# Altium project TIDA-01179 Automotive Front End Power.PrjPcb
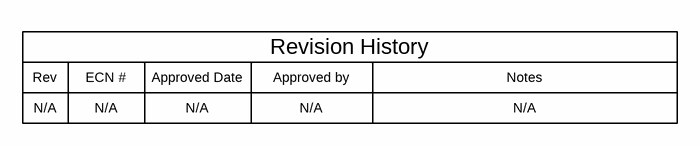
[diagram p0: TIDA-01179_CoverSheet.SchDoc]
CopyrightYear: 2016; PCB_Layout: X.Gong; PCB_Rev: E1; PRJ_Customer: Public Release; PRJ_Engineer: X.Gong; PRJ_Number: TIDA-01179; PRJ_Title: Automotive Wide Vin 30W Front-End Power Reference Design for 12V Car Battery; SCH_Rev: E1; TechSupport: http://www.ti.com/support; TID: 01179
4 sheets, 142 parts. Net scope: global (net labels, ports and power ports of the same name join across sheets).
Board file: TIDA-01179_Project_PCB.PcbDoc
Sheets:
  TIDA-01179_CoverSheet.SchDoc
  TIDA-01179_DCDC_Converters.SchDoc
  TIDA-01179_Reverse_Polarity_Protection.SchDoc
  TIDA-01179_Hardware.SchDoc

## Sheet TIDA-01179_CoverSheet.SchDoc: CoverSheet
size 431 x 279 mm; Date: Not shown in title block; ApprovedBy: Not shown in title block; CheckedBy: Not shown in title block; Author: Not shown in title block; CompanyName: Not shown in title block; DrawnBy: X.Gong; Engineer: Not shown in title block; Organization: Not shown in title block; Address1: Not shown in title block; Address2: Not shown in title block; Address3: Not shown in title block; Address4: Not shown in title block; DocumentNumber: 1; Revision: Use project parameter SCH_Rev; SheetNumber: 1; SheetTotal: 3; PageSetup: Record=PageOptions¦CenterHorizontal=True¦CenterVertical=True¦PrintScale=1.00¦XCorrection=1.00¦YCorrection=1.00¦PrintKind=0¦BorderSize=5000000¦LeftOffset=0¦BottomOffset=0¦Orientation=2¦PaperLength=1000¦PaperWidth=1000¦Scale=100¦PaperSource=15¦PrintQuality=600¦MediaType=1¦DitherType=10¦PaperKind=Letter¦PrintScaleMode=1

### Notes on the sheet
- Rev
- N/A
- ECN #
- Approved Date
- Approved by
- Revision History
- Notes

## Sheet TIDA-01179_DCDC_Converters.SchDoc: DCDC_Converters
size 431 x 279 mm; Date: Not shown in title block; ApprovedBy: Not shown in title block; CheckedBy: Not shown in title block; Author: Not shown in title block; CompanyName: Not shown in title block; DrawnBy: X.Gong; Engineer: Not shown in title block; Organization: Not shown in title block; Address1: Not shown in title block; Address2: Not shown in title block; Address3: Not shown in title block; Address4: Not shown in title block; DocumentNumber: 2; Revision: Use project parameter SCH_Rev; SheetNumber: 2; SheetTotal: 3; PageSetup: Record=PageOptions¦CenterHorizontal=True¦CenterVertical=True¦PrintScale=1.00¦XCorrection=1.00¦YCorrection=1.00¦PrintKind=0¦BorderSize=5000000¦LeftOffset=0¦BottomOffset=0¦Orientation=2¦PaperLength=1000¦PaperWidth=1000¦Scale=100¦PaperSource=15¦PrintQuality=600¦MediaType=1¦DitherType=10¦PaperKind=Letter¦PrintScaleMode=1
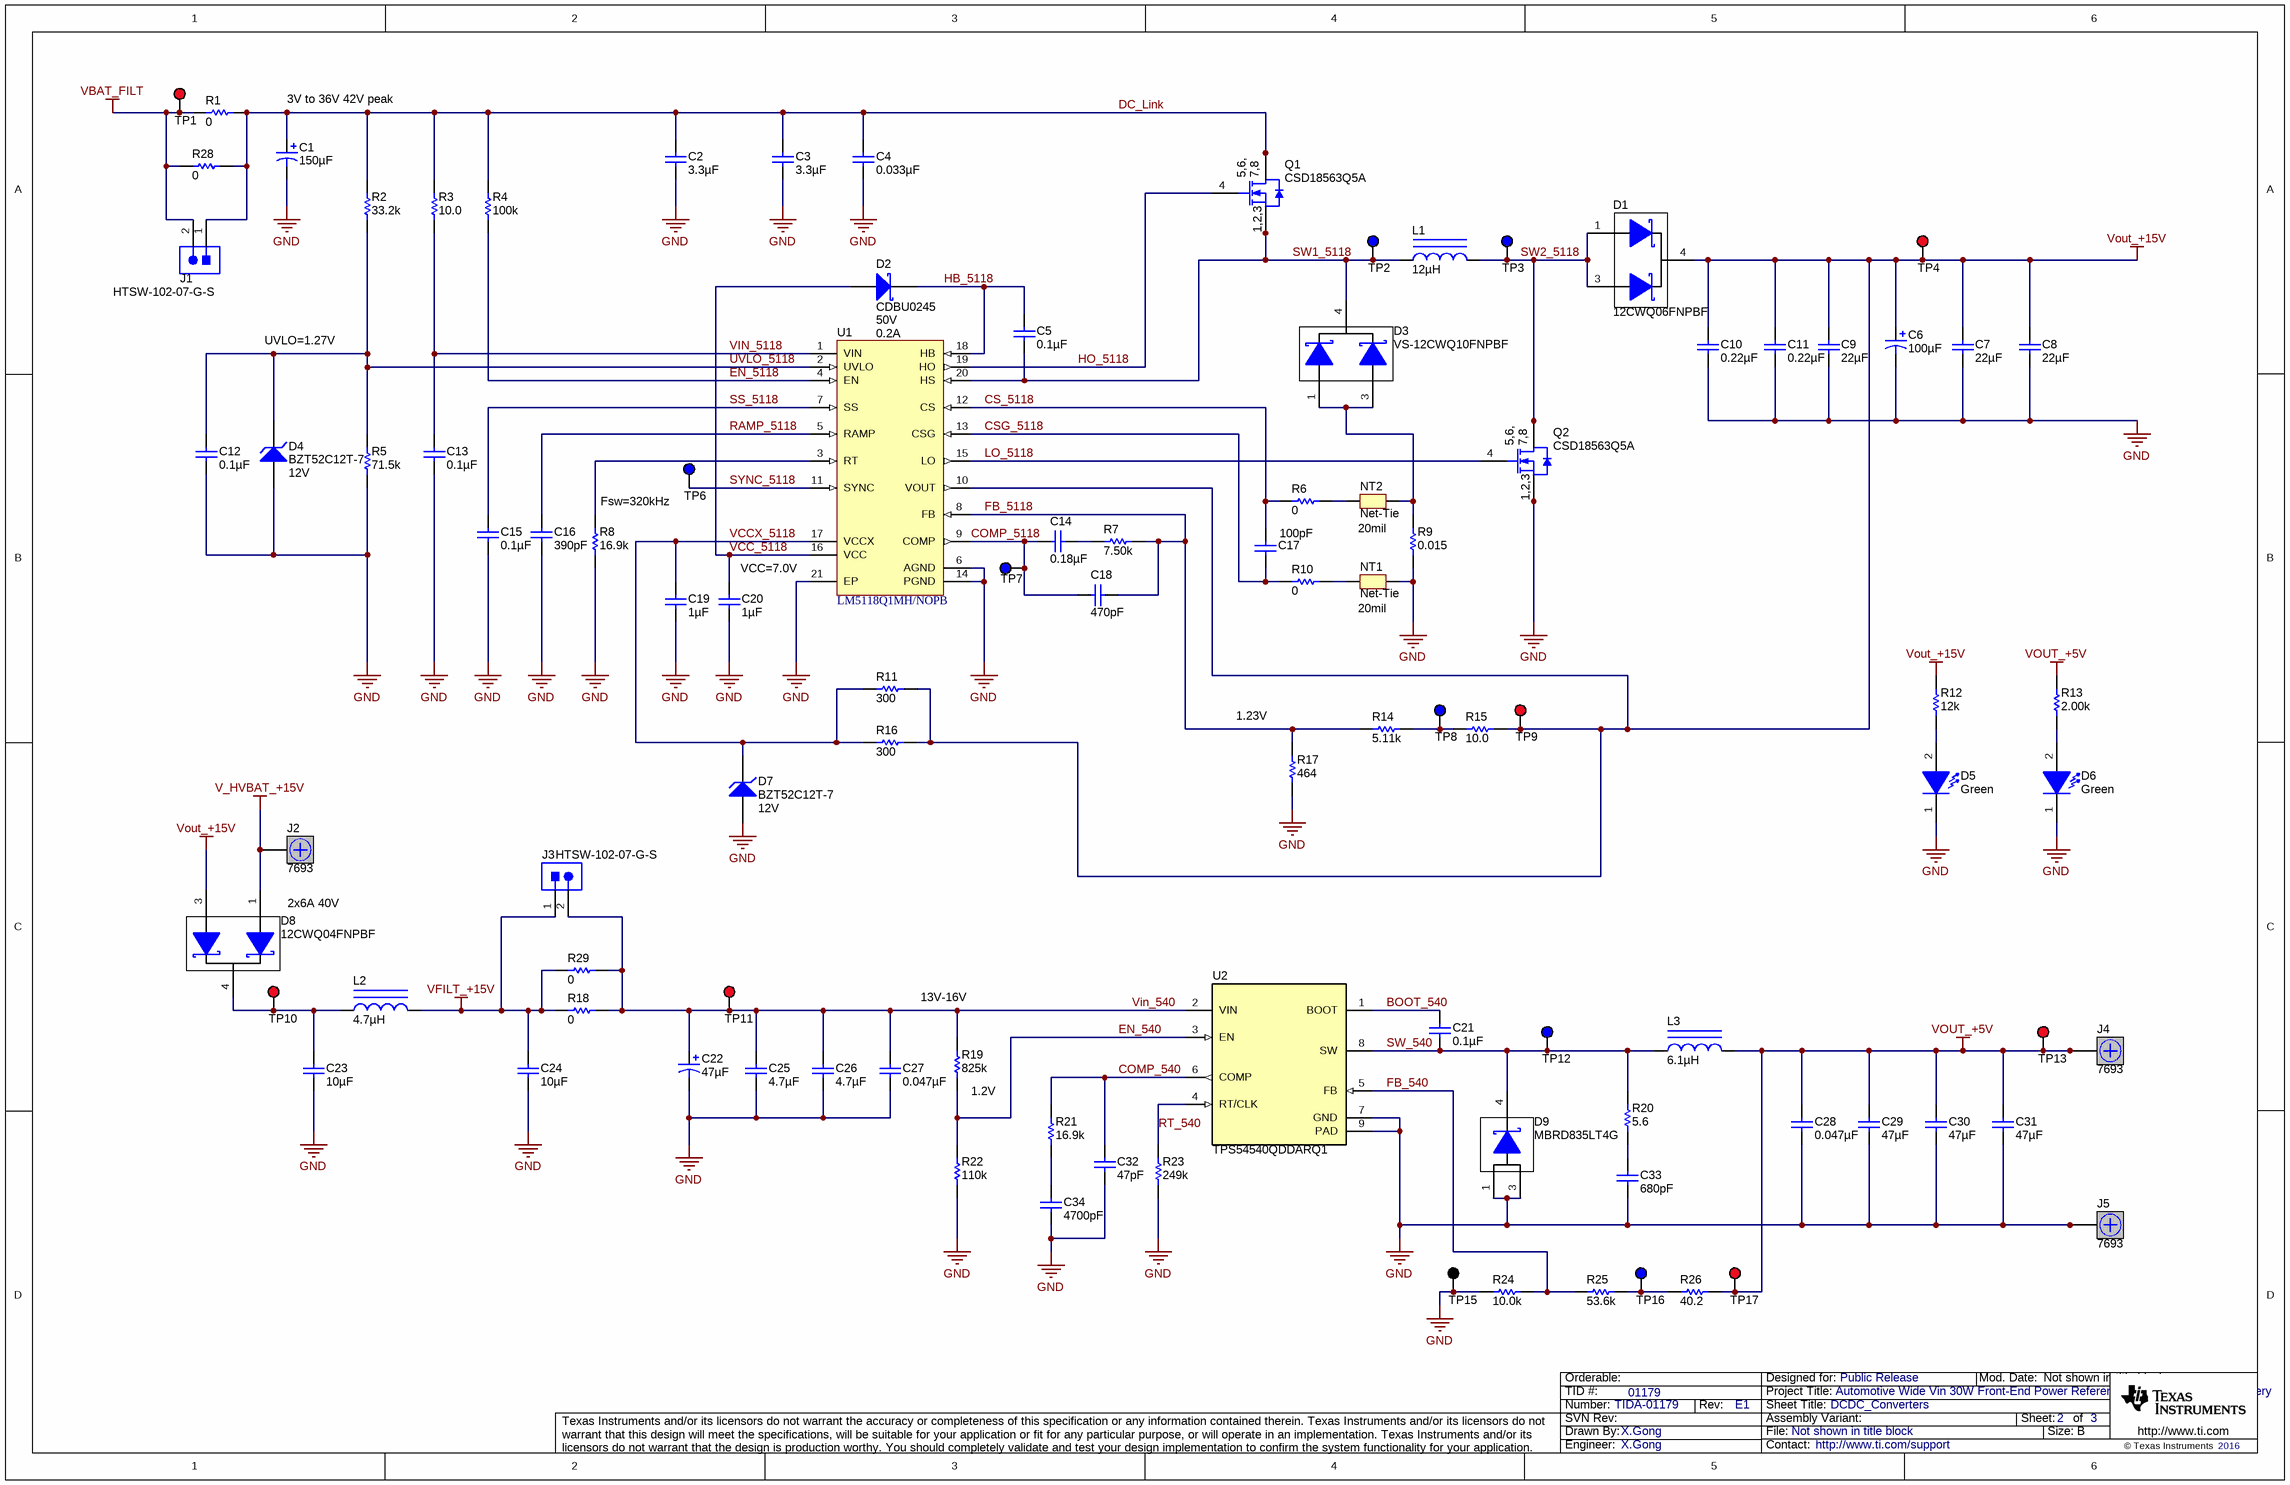
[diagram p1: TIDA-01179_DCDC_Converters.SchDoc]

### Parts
C1  ValueDisplayed: 150µF  [SM_RADIAL_G]  (hidden comment: EEE-FK1H151P)
C2  ValueDisplayed: 3.3µF  [1210_220]  (hidden comment: GRM32DR71H335KA88L)
C3  ValueDisplayed: 3.3µF  [1210_220]  (hidden comment: GRM32DR71H335KA88L)
C4  ValueDisplayed: 0.033µF  [0805_HV]  (hidden comment: GRM219R71H333KA01D)
C5  ValueDisplayed: 0.1µF  [0603]  (hidden comment: GRM188R71E104KA01D)
C6  ValueDisplayed: 100µF  [SM_RADIAL_D8]  (hidden comment: EEE-FK1V101XP)
C7  ValueDisplayed: 22µF  [1210_270]  (hidden comment: GRM32ER71E226KE15L)
C8  ValueDisplayed: 22µF  [1210_270]  (hidden comment: GRM32ER71E226KE15L)
C9  ValueDisplayed: 22µF  [1210_270]  (hidden comment: GRM32ER71E226KE15L)
C10  ValueDisplayed: 0.22µF  [0805_HV]  (hidden comment: GRM219R71E224KA01D)
C11  ValueDisplayed: 0.22µF  [0805_HV]  (hidden comment: GRM219R71E224KA01D)
C12  ValueDisplayed: 0.1µF  [0603]  (hidden comment: GRM188R71E104KA01D)
C13  ValueDisplayed: 0.1µF  [0805_HV]  (hidden comment: GRM21BR71H104KA01L)
C14  ValueDisplayed: 0.18µF  [0603]  (hidden comment: GRM188R71E184KA88D)
C15  ValueDisplayed: 0.1µF  [0603]  (hidden comment: GRM188R71E104KA01D)
C16  ValueDisplayed: 390pF  [0603]  (hidden comment: GRM188R71H391KA01D)
C17  ValueDisplayed: 100pF  [0603]  (hidden comment: GRM1885C1H101JA01D)
C18  ValueDisplayed: 470pF  [0603]  (hidden comment: GCM1885C1H471JA16D)
C19  ValueDisplayed: 1µF  [0805_HV]  (hidden comment: GRM21BR71E105KA99L)
C20  ValueDisplayed: 1µF  [0805_HV]  (hidden comment: GRM21BR71E105KA99L)
C21  ValueDisplayed: 0.1µF  [0603]  (hidden comment: GRM188R71E104KA01D)
C22  ValueDisplayed: 47µF  [SM_RADIAL_D]  (hidden comment: EEE-FK1V470P)
C23  ValueDisplayed: 10µF  [0805_HV]  (hidden comment: GRM21BZ71E106KE15L)
C24  ValueDisplayed: 10µF  [0805_HV]  (hidden comment: GRM21BZ71E106KE15L)
C25  ValueDisplayed: 4.7µF  [0805_HV]  (hidden comment: GRM21BR71E475KA73L)
C26  ValueDisplayed: 4.7µF  [0805_HV]  (hidden comment: GRM21BR71E475KA73L)
C27  ValueDisplayed: 0.047µF  [0805_HV]  (hidden comment: GRM219R71E473KA01D)
C28  ValueDisplayed: 0.047µF  [0805_HV]  (hidden comment: GRM219R71E473KA01D)
C29  ValueDisplayed: 47µF  [1210_270]  (hidden comment: GRM32ER61C476ME15L)
C30  ValueDisplayed: 47µF  [1210_270]  (hidden comment: GRM32ER61C476ME15L)
C31  ValueDisplayed: 47µF  [1210_270]  (hidden comment: GRM32ER61C476ME15L)
C32  ValueDisplayed: 47pF  [0603]  (hidden comment: GRM1885C1H470JA01D)
C33  ValueDisplayed: 680pF  [0603]  (hidden comment: GRM188R71H681KA01D)
C34  ValueDisplayed: 4700pF  [0603]  (hidden comment: GCM188R71H472KA37D)
D1  12CWQ06FNPBF  [DPAK]
D2  CDBU0245  value 50V  Value1: 0.2A  [SOD-523F]
D3  VS-12CWQ10FNPBF  [DPAK]
D4  BZT52C12T-7  value 12V  [SOD-523]
D5  value Green  [WL-SMCW_GREEN]  (hidden comment: 150060GS75000)
D6  value Green  [WL-SMCW_GREEN]  (hidden comment: 150060GS75000)
D7  BZT52C12T-7  value 12V  [SOD-523]
D8  12CWQ04FNPBF  [DPAK]
D9  MBRD835LT4G  [DPAK]
J1  HTSW-102-07-G-S  [Samtec_HTSW-102-07-G-S]
J2  7693  [7693]
J3  HTSW-102-07-G-S  [Samtec_HTSW-102-07-G-S]
J4  7693  [7693]
J5  7693  [7693]
L1  ValueDisplayed: 12µH  [MSS1583]  (hidden comment: MSS1583-123MEB)
L2  ValueDisplayed: 4.7µH  [MSS1260]  (hidden comment: MSS1260-472MLB)
L3  ValueDisplayed: 6.1µH  [SRR1260A]  (hidden comment: SRR1260A-6R1Y)
NT1  Net-Tie  [Net-Tie_20milWide_60milLong]  (net tie, no BOM)
NT2  Net-Tie  [Net-Tie_20milWide_60milLong]  (net tie, no BOM)
Q1  CSD18563Q5A  [TRANS_NexFET_Q5A]
Q2  CSD18563Q5A  [TRANS_NexFET_Q5A]
R1  ValueDisplayed: 0  [2512]  (hidden comment: CRCW25120000Z0EGHP)
R2  ValueDisplayed: 33.2k  [0805_HV]  (hidden comment: CRCW080533K2FKEA)
R3  ValueDisplayed: 10.0  [0805_HV]  (hidden comment: CRCW080510R0FKEA)
R4  ValueDisplayed: 100k  [0805_HV]  (hidden comment: CRCW0805100KFKEA)
R5  ValueDisplayed: 71.5k  [0805_HV]  (hidden comment: CRCW080571K5FKEA)
R6  ValueDisplayed: 0  [0603]  (hidden comment: CRCW06030000Z0EA)
R7  ValueDisplayed: 7.50k  [0603]  (hidden comment: CRCW06037K50FKEA)
R8  ValueDisplayed: 16.9k  [0603]  (hidden comment: CRCW060316K9FKEA)
R9  ValueDisplayed: 0.015  [2512]  (hidden comment: CRA2512-FZ-R015ELF)
R10  ValueDisplayed: 0  [0603]  (hidden comment: CRCW06030000Z0EA)
R11  ValueDisplayed: 300  [1206]  (hidden comment: CRCW1206300RJNEA)
R12  ValueDisplayed: 12k  [0805_HV]  (hidden comment: CRCW080512K0JNEA)
R13  ValueDisplayed: 2.00k  [0805_HV]  (hidden comment: CRCW08052K00FKEA)
R14  ValueDisplayed: 5.11k  [0603]  (hidden comment: CRCW06035K11FKEA)
R15  ValueDisplayed: 10.0  [0603]  (hidden comment: CRCW060310R0FKEA)
R16  ValueDisplayed: 300  [1206]  (hidden comment: CRCW1206300RJNEA)
R17  ValueDisplayed: 464  [0603]  (hidden comment: CRCW0603464RFKEA)
R18  ValueDisplayed: 0  [2512]  (hidden comment: CRCW25120000Z0EGHP)
R19  ValueDisplayed: 825k  [0805_HV]  (hidden comment: CRCW0805825KFKEA)
R20  ValueDisplayed: 5.6  [1206]  (hidden comment: CRCW12065R60JNEA)
R21  ValueDisplayed: 16.9k  [0603]  (hidden comment: CRCW060316K9FKEA)
R22  ValueDisplayed: 110k  [0805_HV]  (hidden comment: CRCW0805110KFKEA)
R23  ValueDisplayed: 249k  [0603]  (hidden comment: CRCW0603249KFKEA)
R24  ValueDisplayed: 10.0k  [0603]  (hidden comment: CRCW060310K0FKEA)
R25  ValueDisplayed: 53.6k  [0603]  (hidden comment: CRCW060353K6FKEA)
R26  ValueDisplayed: 40.2  [0603]  (hidden comment: CRCW060340R2FKEA)
R28  ValueDisplayed: 0  [2512]  (hidden comment: CRCW25120000Z0EGHP)
R29  ValueDisplayed: 0  [2512]  (hidden comment: CRCW25120000Z0EGHP)
TP1  5005  [Keystone5005]  (value not drawn)
TP2  5122  [Keystone5122]  (value not drawn)
TP3  5122  [Keystone5122]  (value not drawn)
TP4  5005  [Keystone5005]  (value not drawn)
TP6  5122  [Keystone5122]  (value not drawn)
TP7  5122  [Keystone5122]  (value not drawn)
TP8  5122  [Keystone5122]  (value not drawn)
TP9  5005  [Keystone5005]  (value not drawn)
TP10  5005  [Keystone5005]  (value not drawn)
TP11  5005  [Keystone5005]  (value not drawn)
TP12  5122  [Keystone5122]  (value not drawn)
TP13  5005  [Keystone5005]  (value not drawn)
TP15  5006  [Keystone5006]  (value not drawn)
TP16  5122  [Keystone5122]  (value not drawn)
TP17  5005  [Keystone5005]  (value not drawn)
U1  LM5118Q1MH/NOPB  [MXA20A_N]
U2  TPS54540QDDARQ1  [DDA0008E_N]

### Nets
GND: C1.2(-) C2.2 C3.2 C4.2 C6.2(-) C7.2 C8.2 C9.2 C10.2 C11.2 C12.2 C13.2 C15.2 C16.2 C19.2 C20.2 C22.2(-) C23.2 C24.2 C25.2 C26.2 C27.2 C28.2 C29.2 C30.2 C31.2 C32.2 C33.2 C34.2 D4.2(A) D5.1(K) D6.1(K) D7.2(A) D9.1(A) D9.3(A) J5.1 J5.2 J5.3 J5.4 NT1.2 Q2.1(S) Q2.2(S) Q2.3(S) R5.1 R8.1 R9.1 R17.1 R22.1 R23.1 R24.1 TP15.1 U1.6(AGND) U1.14(PGND) U1.21(EP) U2.7(GND) U2.9(PAD)
V_HVBAT_+15V: D8.1(A) J2.1 J2.2 J2.3 J2.4
VBAT_FILT: J1.2 R1.1 R28.1 TP1.1
VFILT_+15V: C24.1 J3.1 L2.2 R18.1 R29.1
VOUT_+5V: C28.1 C29.1 C30.1 C31.1 J4.1 J4.2 J4.3 J4.4 L3.2 R13.2 R26.2 TP13.1 TP17.1
Vout_+15V: C6.1(+) C7.1 C8.1 C9.1 C10.1 C11.1 D1.4(K) D8.3(A) R11.2 R12.2 R15.2 R16.2 TP4.1 TP9.1 U1.10(VOUT)
BOOT_540: C21.2 U2.1(BOOT)
COMP_540: C32.1 R21.2 U2.6(COMP)
COMP_5118: C14.2 C18.2 TP7.1 U1.9(COMP)
CS_5118: C17.1 R6.1 U1.12(CS)
CSG_5118: C17.2 R10.1 U1.13(CSG)
DC_Link: C1.1(+) C2.1 C3.1 C4.1 J1.1 Q1.5(D) Q1.6(D) Q1.7(D) Q1.8(D) Q1.9(D) R1.2 R2.2 R3.2 R4.2 R28.2
EN_540: R19.1 R22.2 U2.3(EN)
EN_5118: R4.1 U1.4(EN)
FB_540: R24.2 R25.1 U2.5(FB)
FB_5118: C18.1 R7.2 R14.2 R17.2 U1.8(FB)
HB_5118: C5.1 D2.1(K) U1.18(HB)
HO_5118: Q1.4(G) U1.19(HO)
LO_5118: Q2.4(G) U1.15(LO)
RAMP_5118: C16.1 U1.5(RAMP)
RT_540: R23.2 U2.4(RT/CLK)
SS_5118: C15.1 U1.7(SS)
SW1_5118: C5.2 D3.4(K) L1.1 Q1.1(S) Q1.2(S) Q1.3(S) TP2.1 U1.20(HS)
SW2_5118: D1.1(A) D1.3(A) L1.2 Q2.5(D) Q2.6(D) Q2.7(D) Q2.8(D) Q2.9(D) TP3.1
SW_540: C21.1 D9.4(K) L3.1 R20.2 TP12.1 U2.8(SW)
SYNC_5118: TP6.1 U1.11(SYNC)
UVLO_5118: C12.1 D4.1(K) R2.1 R5.2 U1.2(UVLO)
VCC_5118: C20.1 D2.2(A) U1.16(VCC)
VCCX_5118: C19.1 D7.1(K) R11.1 R16.1 U1.17(VCCX)
Vin_540: C22.1(+) C25.1 C26.1 C27.1 J3.2 R18.2 R19.2 R29.2 TP11.1 U2.2(VIN)
VIN_5118: C13.1 R3.1 U1.1(VIN)
NetC14_1: C14.1 R7.1
NetC23_1: C23.1 D8.4(K) L2.1 TP10.1
NetC33_1: C33.1 R20.1
NetC34_1: C34.1 R21.1
NetD3_1: D3.1(A) D3.3(A) NT2.2 R9.2
NetD5_2: D5.2(A) R12.1
NetD6_2: D6.2(A) R13.1
NetNT1_1: NT1.1 R10.2
NetNT2_1: NT2.1 R6.2
NetR8_2: R8.2 U1.3(RT)
NetR14_1: R14.1 R15.1 TP8.1
NetR25_2: R25.2 R26.1 TP16.1

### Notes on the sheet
- 3V to 36V 42V peak
- UVLO=1.27V
- Fsw=320kHz
- (near C20) VCC=7.0V
- 20mil
- (near NT1) 20mil
- (near R17) 1.23V
- 2x6A 40V
- 13V-16V
- (near R19) 1.2V

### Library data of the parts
C1 = EEE-FK1H151P: CAP, AL, 150 µF, 50 V, +/- 20%, 0.18 ohm, SMD; Manufacturer: Panasonic; Polarized: Y; CompType: Capacitor; Value: 150uF; U/M: EA; Cap_F: 0.00015; Tolerance_%: 20; VDC_V: 50; Value2: 50V; ESR_ohm: 0.18; IRMS_A: 0.67; TaMin_C: -55; TaMax_C: 105; Cap_Case: G; AEC Category: Q200
C2 C3 = GRM32DR71H335KA88L: CAP, CERM, 3.3 µF, 50 V, +/- 10%, X7R, 1210; Manufacturer: MuRata; Polarized: N; CompType: Capacitor; Value: 3.3uF; U/M: EA; Cap_F: 0.0000033; Tolerance_%: 10; ESR_ohm: 0.003; Value1: 0.003 ohm; VDC_V: 50; Value2: 50V; TaMin_C: -55; TaMax_C: 125; Cap_Case: 1210; AEC Category: Q200
C4 = GRM219R71H333KA01D: CAP, CERM, 0.033 µF, 50 V, +/- 10%, X7R, 0805; Manufacturer: MuRata; Polarized: N; CompType: Capacitor; Value: 0.033uF; U/M: EA; Cap_F: 0.000000033; Tolerance_%: 10; Value1: Unknown; VDC_V: 50; Value2: 50V; TaMin_C: -55; TaMax_C: 125; Cap_Case: 0805; AEC Category: Q200
C5 C12 C15 C21 = GRM188R71E104KA01D: CAP, CERM, 0.1 µF, 25 V, +/- 10%, X7R, 0603; Manufacturer: MuRata; Polarized: N; CompType: Capacitor; Value: 0.1uF; U/M: EA; Cap_F: 0.0000001; Tolerance_%: 10; Value1: Unknown; VDC_V: 25; Value2: 25V; TaMin_C: -55; TaMax_C: 125; AEC Category: Q200
C6 = EEE-FK1V101XP: CAP, AL, 100 µF, 35 V, +/- 20%, 0.34 ohm, SMD; Manufacturer: Panasonic; Polarized: Y; CompType: Capacitor; Value: 100uF; U/M: EA; Cap_F: 0.0001; Tolerance_%: 20; VDC_V: 35; Value2: 35V; ESR_ohm: 0.34; IRMS_A: 0.28; TaMin_C: -55; TaMax_C: 105; Cap_Case: D8; AEC Category: Q200
C7-C9 = GRM32ER71E226KE15L: CAP, CERM, 22 µF, 25 V, +/- 10%, X7R, 1210; Manufacturer: MuRata; Polarized: N; CompType: Capacitor; Value: 22uF; U/M: EA; Cap_F: 0.000022; Tolerance_%: 10; Value1: Unknown; VDC_V: 25; Value2: 25V; TaMin_C: -55; TaMax_C: 125; Cap_Case: 1210; AEC Category: Q200
C10 C11 = GRM219R71E224KA01D: CAP, CERM, 0.22 µF, 25 V, +/- 10%, X7R, 0805; Manufacturer: MuRata; Polarized: N; CompType: Capacitor; Value: 0.22uF; U/M: EA; Cap_F: 0.00000022; Tolerance_%: 10; Value1: Unknown; VDC_V: 25; Value2: 25V; TaMin_C: -55; TaMax_C: 125; Cap_Case: 0805; AEC Category: Q200
C13 = GRM21BR71H104KA01L: CAP, CERM, 0.1 µF, 50 V, +/- 10%, X7R, 0805; Manufacturer: MuRata; Polarized: N; CompType: Capacitor; Value: 0.1uF; U/M: EA; Cap_F: 0.0000001; Tolerance_%: 10; Value1: Unknown; VDC_V: 50; Value2: 50V; TaMin_C: -55; TaMax_C: 125; Cap_Case: 0805; AEC Category: Q200
C14 = GRM188R71E184KA88D: CAP, CERM, 0.18 µF, 25 V, +/- 10%, X7R, 0603; Manufacturer: MuRata; Polarized: N; CompType: Capacitor; Value: 0.18uF; U/M: EA; Cap_F: 0.00000018; Tolerance_%: 10; Value1: Unknown; VDC_V: 25; Value2: 25V; TaMin_C: -55; TaMax_C: 125; AEC Category: Q200
C16 = GRM188R71H391KA01D: CAP, CERM, 390 pF, 50 V, +/- 10%, X7R, 0603; Manufacturer: MuRata; Polarized: N; CompType: Capacitor; Value: 390pF; U/M: EA; Cap_F: 0.00000000039; Tolerance_%: 10; Value1: Unknown; VDC_V: 50; Value2: 50V; TaMin_C: -55; TaMax_C: 125; AEC Category: Q200
C17 = GRM1885C1H101JA01D: CAP, CERM, 100 pF, 50 V, +/- 5%, C0G/NP0, 0603; Manufacturer: MuRata; Polarized: N; CompType: Capacitor; Value: 100pF; U/M: EA; Cap_F: 0.0000000001; Tolerance_%: 5; Value1: Unknown; VDC_V: 50; Value2: 50V; TaMin_C: -55; TaMax_C: 125; AEC Category: Q200
C18 = GCM1885C1H471JA16D: CAP, CERM, 470 pF, 50 V, +/- 5%, C0G/NP0, AEC-Q200 Grade 1, 0603; Manufacturer: MuRata; Polarized: N; CompType: Capacitor; Value: 470pF; U/M: EA; Cap_F: 0.00000000047; Tolerance_%: 5; Value1: Unknown; VDC_V: 50; Value2: 50V; TaMin_C: -55; TaMax_C: 125; AEC Category: Q200; AEC Qualified: Y; AEC Grade: 1
C19 C20 = GRM21BR71E105KA99L: CAP, CERM, 1 µF, 25 V, +/- 10%, X7R, 0805; Manufacturer: MuRata; Polarized: N; CompType: Capacitor; Value: 1uF; U/M: EA; Cap_F: 0.000001; Tolerance_%: 10; Value1: Unknown; VDC_V: 25; Value2: 25V; TaMin_C: -55; TaMax_C: 125; Cap_Case: 0805; AEC Category: Q200
C22 = EEE-FK1V470P: CAP, AL, 47 µF, 35 V, +/- 20%, 0.36 ohm, SMD; Manufacturer: Panasonic; Polarized: Y; CompType: Capacitor; Value: 47uF; U/M: EA; Cap_F: 0.000047; Tolerance_%: 20; VDC_V: 35; Value2: 35V; ESR_ohm: 0.36; IRMS_A: 0.24; TaMin_C: -55; TaMax_C: 105; Cap_Case: D; AEC Category: Q200
C23 C24 = GRM21BZ71E106KE15L: CAP, CERM, 10 µF, 25 V, +/- 10%, X7R, 0805; Manufacturer: MuRata; Polarized: N; CompType: Capacitor; Value: 10uF; U/M: EA; Cap_F: 0.00001; Tolerance_%: 10; Value1: Unknown; VDC_V: 25; Value2: 25V; TaMin_C: -55; TaMax_C: 125; Cap_Case: 0805; AEC Category: Q200
C25 C26 = GRM21BR71E475KA73L: CAP, CERM, 4.7 µF, 25 V, +/- 10%, X7R, 0805; Manufacturer: MuRata; Polarized: N; CompType: Capacitor; Value: 4.7uF; U/M: EA; Cap_F: 0.0000047; Tolerance_%: 10; Value1: Unknown; VDC_V: 25; Value2: 25V; TaMin_C: -55; TaMax_C: 125; Cap_Case: 0805; AEC Category: Q200
C27 C28 = GRM219R71E473KA01D: CAP, CERM, 0.047 µF, 25 V, +/- 10%, X7R, 0805; Manufacturer: MuRata; Polarized: N; CompType: Capacitor; Value: 0.047uF; U/M: EA; Cap_F: 0.000000047; Tolerance_%: 10; Value1: Unknown; VDC_V: 25; Value2: 25V; TaMin_C: -55; TaMax_C: 125; Cap_Case: 0805; AEC Category: Q200
C29-C31 = GRM32ER61C476ME15L: CAP, CERM, 47 µF, 16 V, +/- 20%, X5R, 1210; Manufacturer: MuRata; Polarized: N; CompType: Capacitor; Value: 47uF; U/M: EA; Cap_F: 0.000047; Tolerance_%: 20; ESR_ohm: 0.002; Value1: 0.002 ohm; VDC_V: 16; Value2: 16V; TaMin_C: -55; TaMax_C: 85; Cap_Case: 1210; AEC Category: Q200
C32 = GRM1885C1H470JA01D: CAP, CERM, 47 pF, 50 V, +/- 5%, C0G/NP0, 0603; Manufacturer: MuRata; Polarized: N; CompType: Capacitor; Value: 47pF; U/M: EA; Cap_F: 0.000000000047; Tolerance_%: 5; Value1: Unknown; VDC_V: 50; Value2: 50V; TaMin_C: -55; TaMax_C: 125; AEC Category: Q200
C33 = GRM188R71H681KA01D: CAP, CERM, 680 pF, 50 V, +/- 10%, X7R, 0603; Manufacturer: MuRata; Polarized: N; CompType: Capacitor; Value: 680pF; U/M: EA; Cap_F: 0.00000000068; Tolerance_%: 10; Value1: Unknown; VDC_V: 50; Value2: 50V; TaMin_C: -55; TaMax_C: 125; AEC Category: Q200
C34 = GCM188R71H472KA37D: CAP, CERM, 4700 pF, 50 V, +/- 10%, X7R, AEC-Q200 Grade 1, 0603; Manufacturer: MuRata; Polarized: N; CompType: Capacitor; Value: 4700pF; U/M: EA; Cap_F: 0.0000000047; Tolerance_%: 10; Value1: Unknown; VDC_V: 50; Value2: 50V; TaMin_C: -55; TaMax_C: 125; AEC Category: Q200; AEC Qualified: Y; AEC Grade: 1
D1 = 12CWQ06FNPBF: Diode, Schottky, 60 V, 12 A, DPAK; Manufacturer: Vishay-Semiconductor; U/M: EA; Vf_V: 0.79; Value: 60V; Value1: 12A; Value2: 0.79V; Io_A: 12; Vr_V: 60; TJmax_C: 150; RJC_CperW: 1.5; AEC Category: Q101
D2 = CDBU0245: Diode, Schottky, 50 V, 0.2 A, SOD-523F; Manufacturer: Comchip Technology; U/M: EA; Vf_V: 0.55; Value2: 0.55V; Io_A: 0.2; Vr_V: 50; TJmax_C: 125; AEC Category: Q101; AEC Qualified: N
D3 = VS-12CWQ10FNPBF: Diode, Schottky, 100 V, 6 A, DPAK; Manufacturer: Vishay-Semiconductor; U/M: EA; Vf_V: 0.65; Value: 100V; Value1: 6A; Value2: 0.65V; Io_A: 6; Vr_V: 100; TJmax_C: 150; RJC_CperW: 3; AEC Category: Q101
D4 D7 = BZT52C12T-7: Diode, Zener, 12 V, 300 mW, SOD-523; Manufacturer: Diodes Inc.; SymbolCreator: a0412235; U/M: EA; Power_W: 0.3; Vz_V: 12; Value1: 0.3W; RJA_CperW: 417; AEC Category: Q101
D5 D6 = 150060GS75000: LED, Green, SMD; Manufacturer: Wurth Elektronik; Type: InGaN; Vf_V: 3.2; Value2: 3.2V; Io_A: 0.02; Tjmax_C: 85; Value1: W; Angle: 140; U/M: EA
D8 = 12CWQ04FNPBF: Diode, Schottky, 40 V, 12 A, DPAK; Manufacturer: Vishay-Semiconductor; U/M: EA; Vf_V: 0.68; Value: 40V; Value1: 12A; Value2: 0.68V; Io_A: 12; Vr_V: 40; TJmax_C: 150; RJC_CperW: 1.5; AEC Category: Q101
D9 = MBRD835LT4G: Diode, Schottky, 35 V, 8 A, DPAK; Manufacturer: ON Semiconductor; U/M: EA; Vf_V: 0.51; Value: 35V; Value1: 8A; Value2: 0.51V; Io_A: 8; Vr_V: 35; TJmax_C: 150; RJC_CperW: 2.8; AEC Category: Q101
J1 J3 = HTSW-102-07-G-S: Header, 100mil, 2x1, Gold, TH; Manufacturer: Samtec; SymbolCreator: a0412235
J2 J4 J5 = 7693: Terminal screw, vertical, snap-in; Manufacturer: Keystone; SymbolCreator: a0412235; CompType: Screw Terminal
L1 = MSS1583-123MEB: Inductor, Drum Core, Ferrite, 12 µH, 6.3 A, 0.014 ohm, SMD; Manufacturer: Coilcraft; Value: 12uH; Ind_H: 12.0E-6; Imax_A: 6.3; Irms: 6.3A @ 40C rise; Isat: 14.2A @ 30% inductance drop; DCR_ohm: 0.014; Value2: 6.3A; AEC Category: Q200; AEC Qualified: N
L2 = MSS1260-472MLB: Inductor, Shielded Drum Core, Ferrite, 4.7 µH, 7 A, 0.01 ohm, SMD; Manufacturer: Coilcraft; Value: 4.7uH; Ind_H: 4.7E-6; Imax_A: 7; Irms: 7A @ 40C rise; Isat: 10.8A @ 30% inductance drop; DCR_ohm: 0.01; Value2: 7A; AEC Category: Q200
L3 = SRR1260A-6R1Y: Inductor, Shielded Drum Core, Ferrite, 6.1 µH, 6.6 A, 0.017 ohm, AEC-Q200 Grade 1, SMD; Manufacturer: Bourns; Value: 6.1uH; Ind_H: 6.1E-6; Imax_A: 6.6; Irms: 6.6A @ 40C rise; Isat: 6.8A @ 25% inductance drop; DCR_ohm: 0.017; Value2: 6.6A; AEC Category: Q200; AEC Qualified: Y; AEC Grade: 1
NT1 NT2 = Net-Tie: Single point connection between nets.; SymbolCreator: codlsc
Q1 Q2 = CSD18563Q5A: MOSFET, N-CH, 60 V, 15 A, SON 5x6mm; Manufacturer: Texas Instruments; Alternate Manufacturer: None; U/M: EA; ChType: N; Value: 60V; VdsMax_V: 60; Value1: 0.0086 ohm; Rdson45_ohm: 0.0086; Value2: 15 nC; QgTyp_nC: 15; Vgs_V: 20; AEC Category: Q101
R1 R18 R28 R29 = CRCW25120000Z0EGHP: RES, 0, 5%, 1.5 W, AEC-Q200 Grade 0, 2512; Manufacturer: Vishay-Dale; CompType: Resistor; Value: 0; Value_Code: 0000; Tolerance_%: 5; Power_W: 1.5; Value2: 1.5W; TempCo: ppm/C; EIA_Code: E24; U/M: EA; AEC Category: Q200; AEC Qualified: Y
R2 = CRCW080533K2FKEA: RES, 33.2 k, 1%, 0.125 W, 0805; Manufacturer: Vishay-Dale; CompType: Resistor; Value: 33.2k; Res_ohm: 33200; Value_Code: 33k2; Tolerance_%: 1; Power_W: 0.125; Value2: 0.125W; VDC_V: 150; TempCo: 100 ppm/C; EIA_Code: E96; U/M: EA; AEC Category: Q200
R3 = CRCW080510R0FKEA: RES, 10.0, 1%, 0.125 W, 0805; Manufacturer: Vishay-Dale; CompType: Resistor; Value: 10.0; Res_ohm: 10; Value_Code: 10R0; Tolerance_%: 1; Power_W: 0.125; Value2: 0.125W; VDC_V: 150; TempCo: 100 ppm/C; EIA_Code: E96; U/M: EA; AEC Category: Q200
R4 = CRCW0805100KFKEA: RES, 100 k, 1%, 0.125 W, 0805; Manufacturer: Vishay-Dale; CompType: Resistor; Value: 100k; Res_ohm: 100000; Tolerance_%: 1; Power_W: 0.125; Value2: 0.125W; VDC_V: 150; TempCo: 100 ppm/C; EIA_Code: E96; U/M: EA; AEC Category: Q200
R5 = CRCW080571K5FKEA: RES, 71.5 k, 1%, 0.125 W, 0805; Manufacturer: Vishay-Dale; CompType: Resistor; Value: 71.5k; Res_ohm: 71500; Value_Code: 71k5; Tolerance_%: 1; Power_W: 0.125; Value2: 0.125W; VDC_V: 150; TempCo: 100 ppm/C; EIA_Code: E96; U/M: EA; AEC Category: Q200
R6 R10 = CRCW06030000Z0EA: RES, 0, 5%, 0.1 W, 0603; Manufacturer: Vishay-Dale; CompType: Resistor; Value: 0; Value_Code: 0000; Tolerance_%: 5; Power_W: 0.1; Value2: 0.1W; VDC_V: 75; TempCo: 200 ppm/C; EIA_Code: E24; U/M: EA; AEC Category: Q200
R7 = CRCW06037K50FKEA: RES, 7.50 k, 1%, 0.1 W, 0603; Manufacturer: Vishay-Dale; CompType: Resistor; Value: 7.50k; Res_ohm: 7500; Value_Code: 7k50; Tolerance_%: 1; Power_W: 0.1; Value2: 0.1W; VDC_V: 75; TempCo: 100 ppm/C; EIA_Code: E96; U/M: EA; AEC Category: Q200
R8 R21 = CRCW060316K9FKEA: RES, 16.9 k, 1%, 0.1 W, 0603; Manufacturer: Vishay-Dale; CompType: Resistor; Value: 16.9k; Res_ohm: 16900; Value_Code: 16k9; Tolerance_%: 1; Power_W: 0.1; Value2: 0.1W; VDC_V: 75; TempCo: 100 ppm/C; EIA_Code: E96; U/M: EA; AEC Category: Q200
R9 = CRA2512-FZ-R015ELF: RES, 0.015, 1%, 3 W, 2512; Manufacturer: Bourns; CompType: Resistor; Value: 0.015; Value_Code: R015; Tolerance_%: 1; Power_W: 3; Value2: 3W; TempCo: 75 ppm/C; EIA_Code: E96; U/M: EA; AEC Category: Q200
R11 R16 = CRCW1206300RJNEA: RES, 300, 5%, 0.25 W, 1206; Manufacturer: Vishay-Dale; CompType: Resistor; Value: 300; Value_Code: 300R; Tolerance_%: 5; Power_W: 0.25; Value2: 0.25W; VDC_V: 200; TempCo: 200 ppm/C; EIA_Code: E24; U/M: EA; AEC Category: Q200
R12 = CRCW080512K0JNEA: RES, 12 k, 5%, 0.125 W, 0805; Manufacturer: Vishay-Dale; CompType: Resistor; Value: 12k; Res_ohm: 12000; Value_Code: 12k0; Tolerance_%: 5; Power_W: 0.125; Value2: 0.125W; VDC_V: 150; TempCo: 200 ppm/C; EIA_Code: E24; U/M: EA; AEC Category: Q200
R13 = CRCW08052K00FKEA: RES, 2.00 k, 1%, 0.125 W, 0805; Manufacturer: Vishay-Dale; CompType: Resistor; Value: 2.00k; Res_ohm: 2000; Value_Code: 2k00; Tolerance_%: 1; Power_W: 0.125; Value2: 0.125W; VDC_V: 150; TempCo: 100 ppm/C; EIA_Code: E96; U/M: EA; AEC Category: Q200
R14 = CRCW06035K11FKEA: RES, 5.11 k, 1%, 0.1 W, 0603; Manufacturer: Vishay-Dale; CompType: Resistor; Value: 5.11k; Res_ohm: 5110; Value_Code: 5k11; Tolerance_%: 1; Power_W: 0.1; Value2: 0.1W; VDC_V: 75; TempCo: 100 ppm/C; EIA_Code: E96; U/M: EA; AEC Category: Q200
R15 = CRCW060310R0FKEA: RES, 10.0, 1%, 0.1 W, 0603; Manufacturer: Vishay-Dale; CompType: Resistor; Value: 10.0; Res_ohm: 10; Value_Code: 10R0; Tolerance_%: 1; Power_W: 0.1; Value2: 0.1W; VDC_V: 75; TempCo: 100 ppm/C; EIA_Code: E96; U/M: EA; AEC Category: Q200
R17 = CRCW0603464RFKEA: RES, 464, 1%, 0.1 W, 0603; Manufacturer: Vishay-Dale; CompType: Resistor; Value: 464; Value_Code: 464R; Tolerance_%: 1; Power_W: 0.1; Value2: 0.1W; VDC_V: 75; TempCo: 100 ppm/C; EIA_Code: E96; U/M: EA; AEC Category: Q200
R19 = CRCW0805825KFKEA: RES, 825 k, 1%, 0.125 W, 0805; Manufacturer: Vishay-Dale; CompType: Resistor; Value: 825k; Res_ohm: 825000; Tolerance_%: 1; Power_W: 0.125; Value2: 0.125W; VDC_V: 150; TempCo: 100 ppm/C; EIA_Code: E96; U/M: EA; AEC Category: Q200
R20 = CRCW12065R60JNEA: RES, 5.6, 5%, 0.25 W, 1206; Manufacturer: Vishay-Dale; CompType: Resistor; Value: 5.6; Value_Code: 5R60; Tolerance_%: 5; Power_W: 0.25; Value2: 0.25W; VDC_V: 200; TempCo: 200 ppm/C; EIA_Code: E24; U/M: EA; AEC Category: Q200
R22 = CRCW0805110KFKEA: RES, 110 k, 1%, 0.125 W, 0805; Manufacturer: Vishay-Dale; CompType: Resistor; Value: 110k; Res_ohm: 110000; Tolerance_%: 1; Power_W: 0.125; Value2: 0.125W; VDC_V: 150; TempCo: 100 ppm/C; EIA_Code: E96; U/M: EA; AEC Category: Q200
R23 = CRCW0603249KFKEA: RES, 249 k, 1%, 0.1 W, 0603; Manufacturer: Vishay-Dale; CompType: Resistor; Value: 249k; Res_ohm: 249000; Tolerance_%: 1; Power_W: 0.1; Value2: 0.1W; VDC_V: 75; TempCo: 100 ppm/C; EIA_Code: E96; U/M: EA; AEC Category: Q200
R24 = CRCW060310K0FKEA: RES, 10.0 k, 1%, 0.1 W, 0603; Manufacturer: Vishay-Dale; CompType: Resistor; Value: 10.0k; Res_ohm: 10000; Value_Code: 10k0; Tolerance_%: 1; Power_W: 0.1; Value2: 0.1W; VDC_V: 75; TempCo: 100 ppm/C; EIA_Code: E96; U/M: EA; AEC Category: Q200
R25 = CRCW060353K6FKEA: RES, 53.6 k, 1%, 0.1 W, 0603; Manufacturer: Vishay-Dale; CompType: Resistor; Value: 53.6k; Res_ohm: 53600; Value_Code: 53k6; Tolerance_%: 1; Power_W: 0.1; Value2: 0.1W; VDC_V: 75; TempCo: 100 ppm/C; EIA_Code: E96; U/M: EA; AEC Category: Q200
R26 = CRCW060340R2FKEA: RES, 40.2, 1%, 0.1 W, 0603; Manufacturer: Vishay-Dale; CompType: Resistor; Value: 40.2; Value_Code: 40R2; Tolerance_%: 1; Power_W: 0.1; Value2: 0.1W; VDC_V: 75; TempCo: 100 ppm/C; EIA_Code: E96; U/M: EA; AEC Category: Q200
TP1 TP4 TP9-TP11 TP13 TP17 = 5005: Test Point, Compact, Red, TH; Manufacturer: Keystone; CompType: Test Point Loop; ContactFinish: Silver
TP2 TP3 TP6-TP8 TP12 TP16 = 5122: Test Point, Compact, Blue, TH; Manufacturer: Keystone; CompType: Test Point Loop; U/M: EA; ContactFinish: Silver
TP15 = 5006: Test Point, Compact, Black, TH; Manufacturer: Keystone; CompType: Test Point Loop; ContactFinish: Silver
U1 = LM5118Q1MH/NOPB: Wide Voltage Range Buck-Boost Controller, 20-pin TSSOP-EP, Pb-Free; Manufacturer: Texas Instruments; PackageTopMarking: NSUZXYTT*LM5118*Q1MH; PowerWise: N; CompType: Switcher
U2 = TPS54540QDDARQ1: 4.5 V to 42 V Input, 5 A, Step Down DC-DC Converter with Eco-mode™, DDA0008E; Alternate PartNumber: TPS54540QDDAQ1; Manufacturer: Texas Instruments; SymbolCreator: Altium; CompType: IC; U/M: EA

## Sheet TIDA-01179_Reverse_Polarity_Protection.SchDoc: Reverse_Polarity_Protection
size 431 x 279 mm; Date: Not shown in title block; ApprovedBy: Not shown in title block; CheckedBy: Not shown in title block; Author: Not shown in title block; CompanyName: Not shown in title block; DrawnBy: X.Gong; Engineer: Not shown in title block; Organization: Not shown in title block; Address1: Not shown in title block; Address2: Not shown in title block; Address3: Not shown in title block; Address4: Not shown in title block; DocumentNumber: 3; Revision: Use project parameter SCH_Rev; SheetNumber: 3; SheetTotal: 3; PageSetup: Record=PageOptions¦CenterHorizontal=True¦CenterVertical=True¦PrintScale=1.00¦XCorrection=1.00¦YCorrection=1.00¦PrintKind=0¦BorderSize=5000000¦LeftOffset=0¦BottomOffset=0¦Orientation=2¦PaperLength=1000¦PaperWidth=1000¦Scale=100¦PaperSource=15¦PrintQuality=600¦MediaType=1¦DitherType=10¦PaperKind=Letter¦PrintScaleMode=1
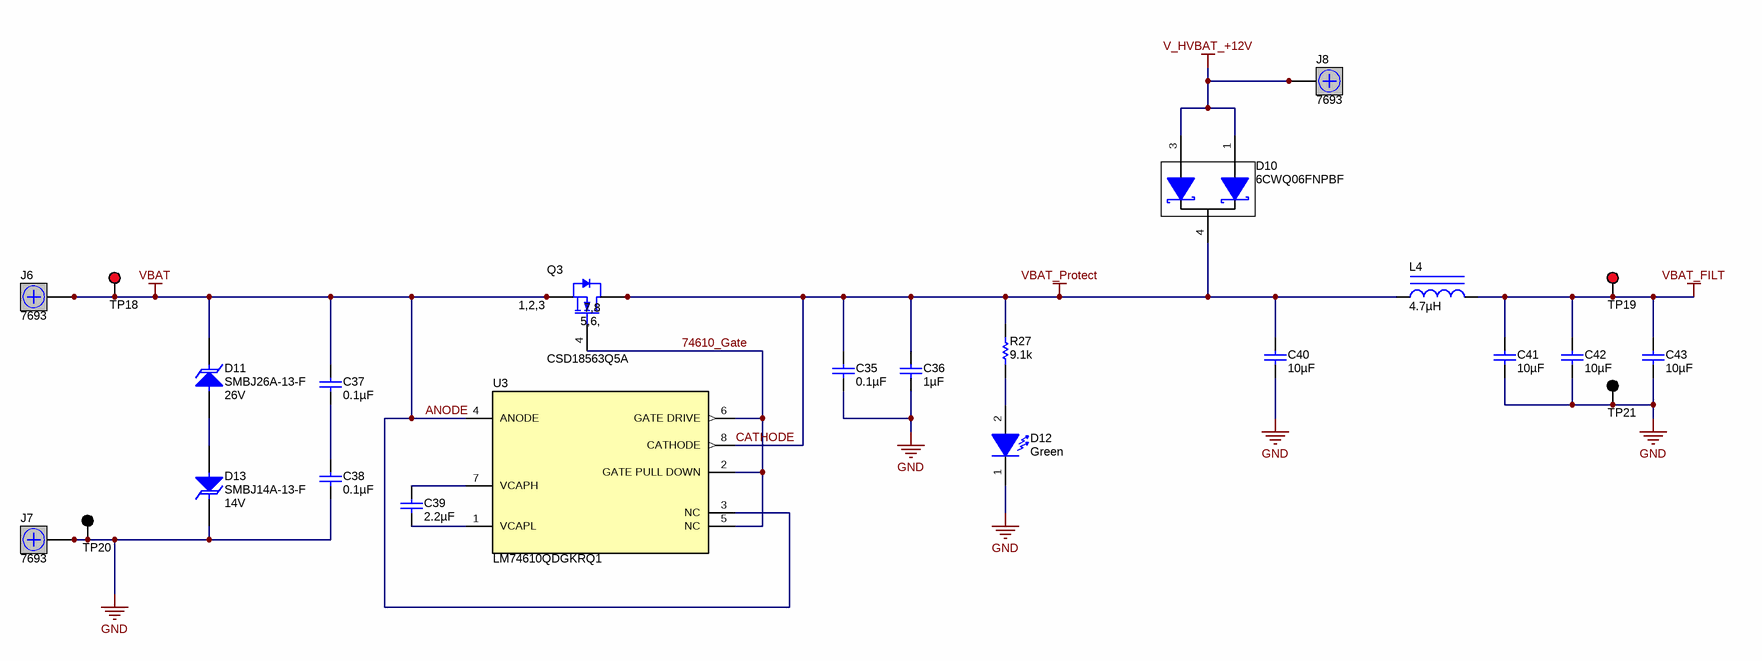
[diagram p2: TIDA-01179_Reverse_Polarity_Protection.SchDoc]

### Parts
C35  ValueDisplayed: 0.1µF  [0603]  (hidden comment: GRM188R71H104KA93D)
C36  ValueDisplayed: 1µF  [0805_HV]  (hidden comment: GRM21BR71H105KA12L)
C37  ValueDisplayed: 0.1µF  [0603]  (hidden comment: GRM188R71H104KA93D)
C38  ValueDisplayed: 0.1µF  [0603]  (hidden comment: GRM188R71H104KA93D)
C39  ValueDisplayed: 2.2µF  [0805_HV]  (hidden comment: C2012X7R1H225K125AC)
C40  ValueDisplayed: 10µF  [1210_270]  (hidden comment: GRM32ER71H106KA12L)
C41  ValueDisplayed: 10µF  [1210_270]  (hidden comment: GRM32ER71H106KA12L)
C42  ValueDisplayed: 10µF  [1210_270]  (hidden comment: GRM32ER71H106KA12L)
C43  ValueDisplayed: 10µF  [1210_270]  (hidden comment: GRM32ER71H106KA12L)
D10  6CWQ06FNPBF  [DPAK]
D11  SMBJ26A-13-F  value 26V  [SMB]
D12  value Green  [WL-SMCW_GREEN]  (hidden comment: 150060GS75000)
D13  SMBJ14A-13-F  value 14V  [SMB]
J6  7693  [7693]
J7  7693  [7693]
J8  7693  [7693]
L4  ValueDisplayed: 4.7µH  [MSS1260]  (hidden comment: MSS1260-472MLB)
Q3  CSD18563Q5A  [TRANS_NexFET_Q5A]
R27  ValueDisplayed: 9.1k  [0805_HV]  (hidden comment: CRCW08059K10JNEA)
TP18  5005  [Keystone5005]  (value not drawn)
TP19  5005  [Keystone5005]  (value not drawn)
TP20  5006  [Keystone5006]  (value not drawn)
TP21  5006  [Keystone5006]  (value not drawn)
U3  LM74610QDGKRQ1  [DGK0008A_N]

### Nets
ANODE: C37.1 D11.1(K) J6.1 J6.2 J6.3 J6.4 Q3.1(S) Q3.2(S) Q3.3(S) TP18.1 U3.3(NC) U3.4(ANODE)  [also labelled VBAT]
CATHODE: C35.1 C36.1 C40.1 D10.4(K) L4.1 Q3.5(D) Q3.6(D) Q3.7(D) Q3.8(D) Q3.9(D) R27.2 U3.8(CATHODE)  [also labelled VBAT_Protect]
GND: C35.2 C36.2 C38.2 C40.2 C41.2 C42.2 C43.2 D12.1(K) D13.1(K) J7.1 J7.2 J7.3 J7.4 TP20.1 TP21.1
V_HVBAT_+12V: D10.1(A) D10.3(A) J8.1 J8.2 J8.3 J8.4
VBAT_FILT: C41.1 C42.1 C43.1 L4.2 TP19.1
74610_Gate: Q3.4(G) U3.2(GATE_PULL_DOWN) U3.5(NC) U3.6(GATE_DRIVE)
NetC37_2: C37.2 C38.1
NetC39_1: C39.1 U3.7(VCAPH)
NetC39_2: C39.2 U3.1(VCAPL)
NetD11_2: D11.2(A) D13.2(A)
NetD12_2: D12.2(A) R27.1

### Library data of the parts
C35 C37 C38 = GRM188R71H104KA93D: CAP, CERM, 0.1 µF, 50 V, +/- 10%, X7R, 0603; Manufacturer: MuRata; Polarized: N; CompType: Capacitor; Value: 0.1uF; U/M: EA; Cap_F: 0.0000001; Tolerance_%: 10; Value1: Unknown; VDC_V: 50; Value2: 50V; TaMin_C: -55; TaMax_C: 125; AEC Category: Q200
C36 = GRM21BR71H105KA12L: CAP, CERM, 1 µF, 50 V, +/- 10%, X7R, 0805; Manufacturer: MuRata; Polarized: N; CompType: Capacitor; Value: 1uF; U/M: EA; Cap_F: 0.000001; Tolerance_%: 10; Value1: Unknown; VDC_V: 50; Value2: 50V; TaMin_C: -55; TaMax_C: 125; Cap_Case: 0805; AEC Category: Q200
C39 = C2012X7R1H225K125AC: CAP, CERM, 2.2 µF, 50 V, +/- 10%, X7R, 0805; Manufacturer: TDK; Polarized: N; CompType: Capacitor; Value: 2.2uF; U/M: EA; Cap_F: 0.0000022; Tolerance_%: 10; Value1: Unknown; VDC_V: 50; Value2: 50V; TaMin_C: -55; TaMax_C: 125; Cap_Case: 0805; AEC Category: Q200
C40-C43 = GRM32ER71H106KA12L: CAP, CERM, 10 µF, 50 V, +/- 10%, X7R, 1210; Manufacturer: MuRata; Polarized: N; CompType: Capacitor; Value: 10uF; U/M: EA; Cap_F: 0.00001; Tolerance_%: 10; Value1: Unknown; VDC_V: 50; Value2: 50V; TaMin_C: -55; TaMax_C: 125; Cap_Case: 1210; AEC Category: Q200
D10 = 6CWQ06FNPBF: Diode, Schottky, 60 V, 7 A, DPAK; Manufacturer: Vishay-Semiconductor; U/M: EA; Vf_V: 0.76; Value: 60V; Value1: 7A; Value2: 0.76V; Io_A: 7; Vr_V: 60; TJmax_C: 150; RJC_CperW: 2.35; AEC Category: Q101
D11 = SMBJ26A-13-F: Diode, TVS, Uni, 26 V, 600 W, SMB; Manufacturer: Diodes Inc.; U/M: EA; Power_W: 5; Vr_V: 26; Value1: 5W; AEC Category: Q101
D12 = 150060GS75000: as D5 on sheet TIDA-01179_DCDC_Converters
D13 = SMBJ14A-13-F: Diode, TVS, Uni, 14 V, 600 W, SMB; Manufacturer: Diodes Inc.; U/M: EA; Power_W: 5; Vr_V: 14; Value1: 5W; AEC Category: Q101
J6-J8 = 7693: as J2 on sheet TIDA-01179_DCDC_Converters
L4 = MSS1260-472MLB: as L2 on sheet TIDA-01179_DCDC_Converters
Q3 = CSD18563Q5A: as Q1 on sheet TIDA-01179_DCDC_Converters
R27 = CRCW08059K10JNEA: RES, 9.1 k, 5%, 0.125 W, 0805; Manufacturer: Vishay-Dale; CompType: Resistor; Value: 9.1k; Res_ohm: 9100; Value_Code: 9k10; Tolerance_%: 5; Power_W: 0.125; Value2: 0.125W; VDC_V: 150; TempCo: 200 ppm/C; EIA_Code: E24; U/M: EA; AEC Category: Q200
TP18 TP19 = 5005: as TP1 on sheet TIDA-01179_DCDC_Converters
TP20 TP21 = 5006: as TP15 on sheet TIDA-01179_DCDC_Converters
U3 = LM74610QDGKRQ1: Smart Diode Controller, DGK0008A; Manufacturer: Texas Instruments; SymbolCreator: Altium; SizeX_mm: 5.05; SizeY_mm: 3.1; SizeZ_mm: 1.1; CompType: IC; U/M: EA

## Sheet TIDA-01179_Hardware.SchDoc: Hardware
size 431 x 279 mm; Date: Not shown in title block; ApprovedBy: Not shown in title block; CheckedBy: Not shown in title block; Author: Not shown in title block; CompanyName: Not shown in title block; DrawnBy: X.Gong; Engineer: Not shown in title block; Organization: Not shown in title block; Address1: Not shown in title block; Address2: Not shown in title block; Address3: Not shown in title block; Address4: Not shown in title block; DocumentNumber: 4; Revision: Use project parameter SCH_Rev; SheetNumber: 4; SheetTotal: 3; PageSetup: Record=PageOptions¦CenterHorizontal=True¦CenterVertical=True¦PrintScale=1.00¦XCorrection=1.00¦YCorrection=1.00¦PrintKind=0¦BorderSize=5000000¦LeftOffset=0¦BottomOffset=0¦Orientation=2¦PaperLength=1000¦PaperWidth=1000¦Scale=100¦PaperSource=15¦PrintQuality=600¦MediaType=1¦DitherType=10¦PaperKind=Letter¦PrintScaleMode=1
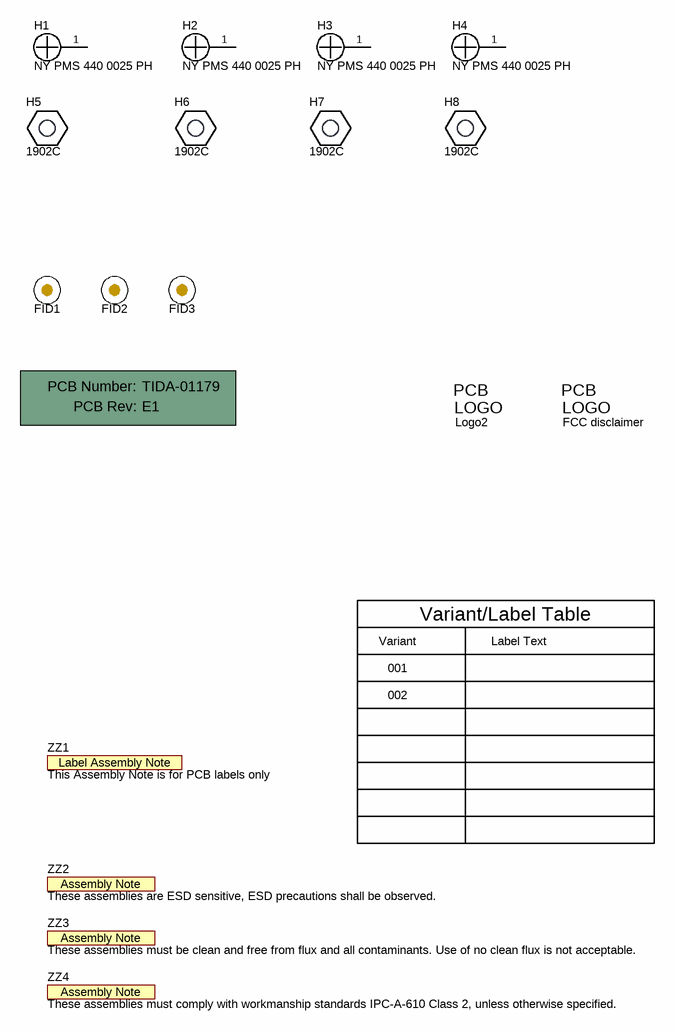
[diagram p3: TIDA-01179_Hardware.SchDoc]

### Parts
!PCB  Printed Circuit Board  (value not drawn)  (mechanical)
FID1  Fiducial  [Fiducial10-20]  (value not drawn)
FID2  Fiducial  [Fiducial10-20]  (value not drawn)
FID3  Fiducial  [Fiducial10-20]  (value not drawn)
H1  NY PMS 440 0025 PH  [NY PMS 440 0025 PH]
H2  NY PMS 440 0025 PH  [NY PMS 440 0025 PH]
H3  NY PMS 440 0025 PH  [NY PMS 440 0025 PH]
H4  NY PMS 440 0025 PH  [NY PMS 440 0025 PH]
H5  1902C  [Keystone_1902C]
H6  1902C  [Keystone_1902C]
H7  1902C  [Keystone_1902C]
H8  1902C  [Keystone_1902C]
Logo2  EU RoHS Exempt Logo  [EURoHS_Exempt_60mil]  (value not drawn)  (no BOM)
Logo3  FCC disclaimer  [FCC_disclaimer]  (no BOM)
ZZ1  This Assembly Note is for PCB labels only  [AssemblyNoteLabel]  (no BOM)
ZZ2  These assemblies are ESD sensitive, ESD precautions shall be observed.  [AssemblyNote]  (no BOM)
ZZ3  These assemblies must be clean and free from flux and all contaminants. Use of no clean flux is not acceptable.  [AssemblyNote]  (no BOM)
ZZ4  These assemblies must comply with workmanship standards IPC-A-610 Class 2, unless otherwise specified.  [AssemblyNote]  (no BOM)

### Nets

Not connected (* = marked no-connect by the designer): H1 1; H2 1; H3 1; H4 1

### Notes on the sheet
- Variant
- Variant/Label Table
- Label Text
- 001
- 002

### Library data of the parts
!PCB = PCB: Manufacturer: Any; PartNumber: TIDA-01179; SymbolCreator: a0412235
FID1-FID3 = Fiducial: Fiducial mark.  There is nothing to buy or mount.; SymbolCreator: codlsc
H1-H4 = NY PMS 440 0025 PH: Machine Screw, Round, #4-40 x 1/4, Nylon, Philips panhead; Manufacturer: B&F Fastener Supply; CompType: Hardware; SymbolCreator: codlsc; U/M: EA
H5-H8 = 1902C: Standoff, Hex, 0.5"L #4-40 Nylon; Manufacturer: Keystone; CompType: Hardware
Logo2 = EURoHS_Exempt: SymbolCreator: a0412235
Logo3 = FCC_disclaimer: SymbolCreator: codlsc
ZZ1 = AssemblyNoteLabel: SymbolCreator: a0412235
ZZ2-ZZ4 = AssemblyNote: SymbolCreator: codlsc

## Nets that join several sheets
GND: TIDA-01179_DCDC_Converters (56 pins), TIDA-01179_Reverse_Polarity_Protection (15 pins)
VBAT_FILT: TIDA-01179_DCDC_Converters (J1.2 R1.1 R28.1 TP1.1), TIDA-01179_Reverse_Polarity_Protection (5 pins)

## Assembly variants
001: not fitted FID1 FID2 FID3 R1 R18 R28 R29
